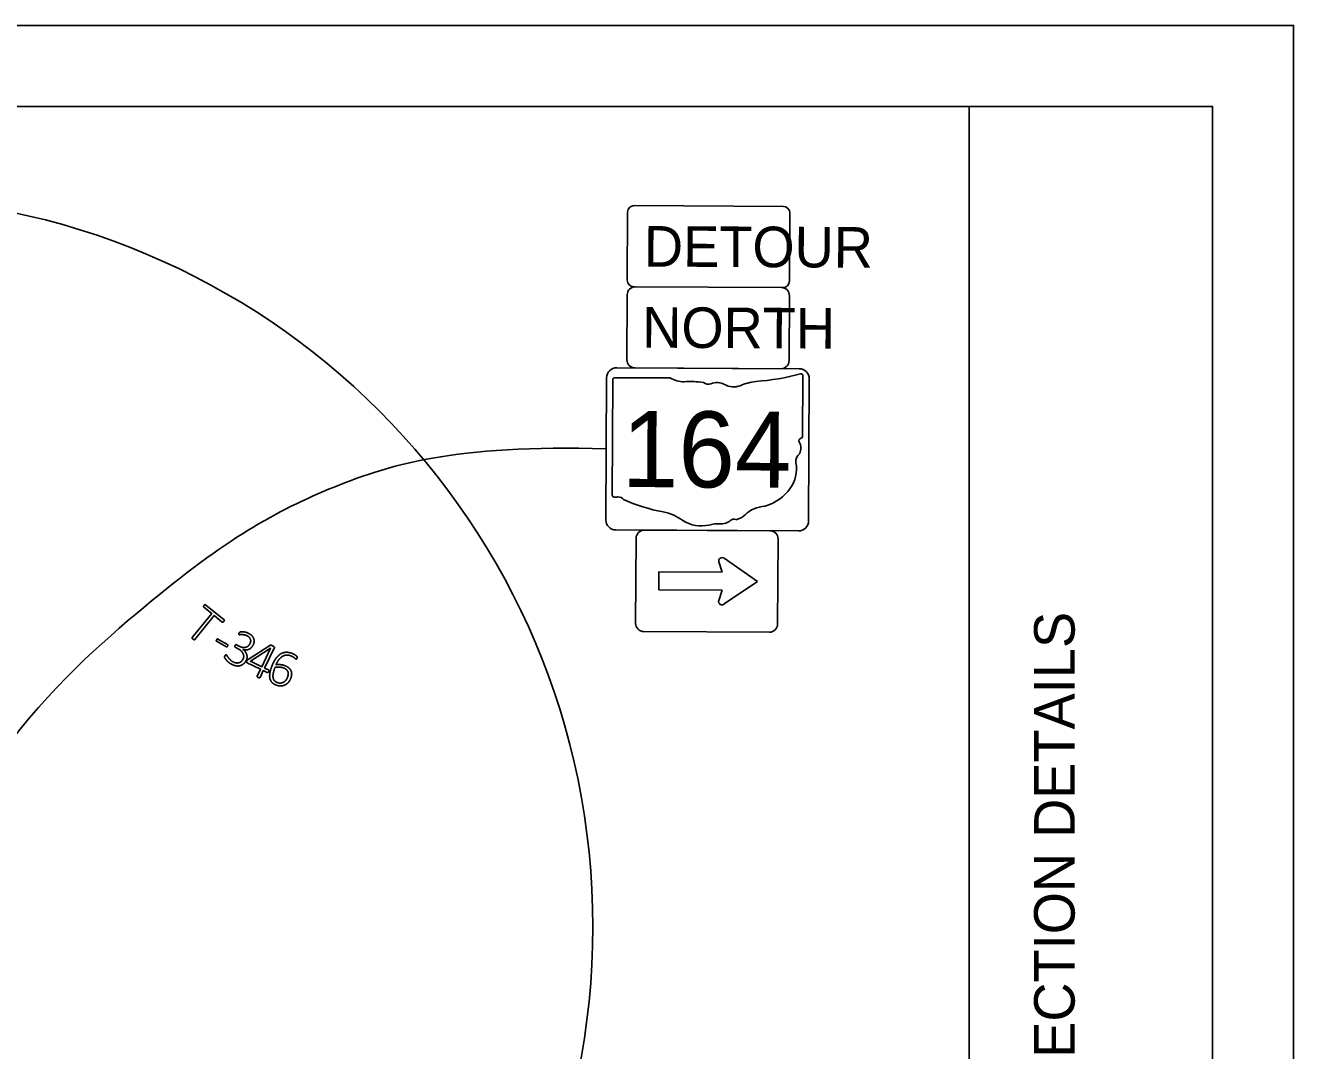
# Model space of a CAD drawing. Extents: x -202 to 1556, y 0 to 676.
# Drawn here: x 523.6 to 680, y 313.6 to 440 of the extents above; entities that cross this region are included whole.
import ezdxf

# ---------------------------------------------------------------- set-up
doc = ezdxf.new("R2010")
doc.units = 0
for name, color, linetype in [('Default', 7, 'Continuous'), ('GM_X_Minor_Lake', 7, 'Continuous'), ('GM_X_Minor_Lake_Text', 7, 'Continuous'), ('SH_Border', 7, 'Continuous'), ('SH_Cut_Line', 7, 'Continuous'), ('SH_Data', 7, 'Continuous')]:
    doc.layers.add(name, color=color, linetype=linetype)

msp = doc.modelspace()

# ---------------------------------------------------------------- linework, layer by layer
at = {"layer": 'Default'}
for p, q in [((545.84, 368.55), (548.12, 366.71)), ((548.09, 366.5), (548.09, 366.5)), ((548.4, 363.37), (547.2, 364.05)), ((547.36, 364.33), (548.56, 363.66)), ((548.56, 363.47), (548.56, 363.47)), ((549.86, 363.13), (549.5, 363.33)), ((549.67, 363.63), (549.99, 363.45)), ((550.45, 363.05), (550.45, 363.04)), ((553.76, 363.55), (551.1, 361.82)), ((550.83, 361.65), (550.83, 361.65)), ((553.63, 360.32), (553.63, 360.32)), ((555.93, 359.59), (555.93, 359.59)), ((556.34, 359.47), (556.34, 359.47))]:
    msp.add_line(p, q, dxfattribs=at)
for points in [[(544.2, 364.51), (546.6, 367.48), (545.62, 368.28)], [(547.9, 366.43), (546.91, 367.23), (544.51, 364.26)], [(553.59, 360.52), (553.11, 360.75), (554.32, 363.28)], [(550.96, 361.41), (552.61, 360.62), (552.19, 359.75)], [(552.55, 359.58), (552.96, 360.45), (553.45, 360.21)]]:
    msp.add_lwpolyline(points, dxfattribs=at)
msp.add_lwpolyline([(553.86, 363.21), (552.76, 360.92), (551.37, 361.59), (553.85, 363.21)], close=True, dxfattribs=at)
for points in [[(545.59, 368.36), (545.59, 368.38), (545.61, 368.41)], [(545.59, 368.31), (545.59, 368.34), (545.59, 368.36)], [(545.62, 368.28), (545.6, 368.29), (545.59, 368.31)], [(545.61, 368.41), (545.62, 368.44), (545.65, 368.48)], [(545.65, 368.48), (545.68, 368.51), (545.71, 368.53)], [(545.71, 368.53), (545.73, 368.56), (545.76, 368.57)], [(545.76, 368.57), (545.78, 368.58), (545.8, 368.57)], [(545.8, 368.57), (545.82, 368.57), (545.84, 368.55)], [(547.94, 366.41), (547.91, 366.41), (547.9, 366.43)], [(547.98, 366.42), (547.96, 366.41), (547.94, 366.41)], [(548.03, 366.45), (548.01, 366.42), (547.98, 366.42)], [(548.09, 366.5), (548.06, 366.47), (548.03, 366.45)], [(548.13, 366.57), (548.11, 366.54), (548.09, 366.5)], [(548.12, 366.71), (548.14, 366.69), (548.15, 366.67)], [(548.15, 366.62), (548.15, 366.6), (548.13, 366.57)], [(548.15, 366.67), (548.16, 366.65), (548.15, 366.62)], [(544.18, 364.48), (544.18, 364.5), (544.2, 364.51)], [(544.19, 364.44), (544.18, 364.46), (544.18, 364.48)], [(544.23, 364.39), (544.2, 364.42), (544.19, 364.44)], [(544.3, 364.32), (544.25, 364.36), (544.23, 364.39)], [(549.92, 364.94), (549.92, 364.96), (549.93, 364.99)], [(549.93, 364.9), (549.92, 364.91), (549.92, 364.94)], [(549.93, 364.99), (549.94, 365.02), (549.97, 365.07)], [(549.96, 364.88), (549.94, 364.89), (549.93, 364.9)], [(550.09, 364.87), (549.99, 364.86), (549.96, 364.88)], [(549.97, 365.07), (549.99, 365.1), (550.01, 365.13)], [(550.01, 365.13), (550.02, 365.15), (550.04, 365.16)], [(550.04, 365.16), (550.06, 365.18), (550.08, 365.19)], [(550.08, 365.19), (550.11, 365.2), (550.15, 365.21)], [(550.33, 364.88), (550.18, 364.88), (550.09, 364.87)], [(550.15, 365.21), (550.19, 365.22), (550.29, 365.23)], [(550.29, 365.23), (550.4, 365.24), (550.55, 365.22)], [(550.65, 364.85), (550.47, 364.88), (550.33, 364.88)], [(550.55, 365.22), (550.69, 365.2), (550.86, 365.15)], [(550.99, 364.72), (550.82, 364.82), (550.65, 364.85)], [(550.86, 365.15), (551.03, 365.1), (551.19, 365.01)], [(551.25, 364.51), (551.16, 364.63), (550.99, 364.72)], [(551.19, 365.01), (551.45, 364.86), (551.6, 364.69)], [(551.38, 364.26), (551.35, 364.39), (551.25, 364.51)], [(551.6, 364.69), (551.74, 364.52), (551.8, 364.33)], [(544.38, 364.27), (544.34, 364.29), (544.3, 364.32)], [(544.43, 364.24), (544.41, 364.25), (544.38, 364.27)], [(544.48, 364.24), (544.46, 364.23), (544.43, 364.24)], [(544.51, 364.26), (544.49, 364.25), (544.48, 364.24)], [(547.16, 364.11), (547.15, 364.16), (547.2, 364.24)], [(547.2, 364.05), (547.16, 364.07), (547.16, 364.11)], [(547.2, 364.24), (547.24, 364.32), (547.28, 364.34)], [(547.28, 364.34), (547.32, 364.36), (547.36, 364.33)], [(548.47, 363.37), (548.43, 363.35), (548.4, 363.37)], [(548.56, 363.47), (548.51, 363.39), (548.47, 363.37)], [(548.56, 363.66), (548.58, 363.65), (548.59, 363.63)], [(548.59, 363.54), (548.58, 363.51), (548.56, 363.47)], [(548.59, 363.63), (548.6, 363.62), (548.6, 363.59)], [(548.6, 363.59), (548.6, 363.57), (548.59, 363.54)], [(549.45, 363.41), (549.44, 363.44), (549.45, 363.47)], [(549.45, 363.47), (549.45, 363.51), (549.48, 363.55)], [(549.47, 363.36), (549.45, 363.38), (549.45, 363.41)], [(549.5, 363.33), (549.48, 363.34), (549.47, 363.36)], [(549.48, 363.55), (549.5, 363.59), (549.52, 363.61)], [(549.52, 363.61), (549.55, 363.63), (549.57, 363.64)], [(549.57, 363.64), (549.6, 363.65), (549.62, 363.65)], [(549.62, 363.65), (549.64, 363.65), (549.67, 363.63)], [(550.25, 362.84), (550.09, 363), (549.86, 363.13)], [(549.99, 363.45), (550.19, 363.34), (550.38, 363.3)], [(550.47, 362.51), (550.4, 362.68), (550.25, 362.84)], [(550.38, 363.3), (550.57, 363.26), (550.74, 363.3)], [(550.82, 362.98), (550.64, 362.98), (550.45, 363.05)], [(550.45, 363.04), (550.63, 362.92), (550.75, 362.75)], [(550.74, 363.3), (550.92, 363.34), (551.06, 363.44)], [(551.15, 363.05), (551, 362.99), (550.82, 362.98)], [(551.06, 363.44), (551.2, 363.55), (551.3, 363.73)], [(551.45, 363.25), (551.31, 363.12), (551.15, 363.05)], [(551.3, 363.73), (551.37, 363.85), (551.39, 363.99)], [(551.39, 363.99), (551.42, 364.13), (551.38, 364.26)], [(551.68, 363.55), (551.58, 363.37), (551.45, 363.25)], [(551.82, 363.94), (551.79, 363.74), (551.68, 363.55)], [(551.8, 364.33), (551.85, 364.14), (551.82, 363.94)], [(553.81, 363.57), (553.78, 363.57), (553.76, 363.55)], [(553.88, 363.57), (553.84, 363.58), (553.81, 363.57)], [(553.97, 363.55), (553.92, 363.57), (553.88, 363.57)], [(554.08, 363.5), (554.02, 363.53), (553.97, 363.55)], [(554.2, 363.44), (554.15, 363.47), (554.08, 363.5)], [(554.28, 363.38), (554.25, 363.41), (554.2, 363.44)], [(554.32, 363.32), (554.31, 363.35), (554.28, 363.38)], [(554.32, 363.28), (554.33, 363.3), (554.32, 363.32)], [(548.18, 362.09), (548.18, 362.12), (548.19, 362.14)], [(548.19, 362.04), (548.18, 362.07), (548.18, 362.09)], [(548.19, 362.14), (548.19, 362.17), (548.21, 362.2)], [(548.26, 361.92), (548.2, 362.01), (548.19, 362.04)], [(548.21, 362.2), (548.22, 362.24), (548.25, 362.28)], [(548.25, 362.28), (548.29, 362.37), (548.33, 362.39)], [(548.42, 361.72), (548.32, 361.83), (548.26, 361.92)], [(548.33, 362.39), (548.37, 362.41), (548.4, 362.39)], [(548.4, 362.39), (548.42, 362.38), (548.48, 362.29)], [(548.66, 361.48), (548.52, 361.6), (548.42, 361.72)], [(548.48, 362.29), (548.53, 362.19), (548.62, 362.07)], [(548.62, 362.07), (548.71, 361.94), (548.85, 361.8)], [(548.98, 361.26), (548.8, 361.36), (548.66, 361.48)], [(548.85, 361.8), (548.98, 361.66), (549.18, 361.54)], [(549.56, 361.03), (549.29, 361.09), (548.98, 361.26)], [(549.18, 361.54), (549.39, 361.43), (549.57, 361.39)], [(549.57, 361.39), (549.76, 361.36), (549.92, 361.4)], [(549.92, 361.4), (550.08, 361.44), (550.21, 361.54)], [(550.5, 361.26), (550.31, 361.1), (550.08, 361.04)], [(550.21, 361.54), (550.34, 361.65), (550.43, 361.81)], [(550.43, 361.81), (550.53, 361.98), (550.54, 362.16)], [(550.54, 362.16), (550.55, 362.33), (550.47, 362.51)], [(550.83, 361.65), (550.7, 361.41), (550.5, 361.26)], [(550.75, 362.75), (550.87, 362.58), (550.92, 362.4)], [(550.95, 362.02), (550.93, 361.83), (550.83, 361.65)], [(550.92, 361.62), (550.9, 361.57), (550.89, 361.54)], [(550.89, 361.54), (550.89, 361.51), (550.9, 361.48)], [(550.9, 361.48), (550.9, 361.46), (550.92, 361.44)], [(550.92, 362.4), (550.97, 362.22), (550.95, 362.02)], [(550.96, 361.69), (550.94, 361.66), (550.92, 361.62)], [(550.92, 361.44), (550.94, 361.42), (550.96, 361.41)], [(551, 361.74), (550.98, 361.71), (550.96, 361.69)], [(551.04, 361.78), (551.02, 361.76), (551, 361.74)], [(551.1, 361.82), (551.07, 361.8), (551.04, 361.78)], [(554.26, 361.55), (554.13, 361.29), (554.03, 361.03)], [(554.56, 362.01), (554.4, 361.8), (554.26, 361.55)], [(554.52, 361.16), (554.65, 361.47), (554.83, 361.73)], [(554.93, 362.38), (554.73, 362.22), (554.56, 362.01)], [(554.83, 361.73), (555.01, 361.98), (555.24, 362.15)], [(555.37, 362.63), (555.13, 362.55), (554.93, 362.38)], [(555.24, 362.15), (555.47, 362.31), (555.74, 362.35)], [(555.89, 362.7), (555.61, 362.71), (555.37, 362.63)], [(555.74, 362.35), (556.01, 362.39), (556.32, 362.27)], [(556.49, 362.57), (556.16, 362.69), (555.89, 362.7)], [(556.32, 362.27), (556.48, 362.21), (556.59, 362.14)], [(556.71, 362.47), (556.6, 362.53), (556.49, 362.57)], [(556.59, 362.14), (556.7, 362.08), (556.78, 362.02)], [(556.9, 362.35), (556.81, 362.41), (556.71, 362.47)], [(556.78, 362.02), (556.85, 361.96), (556.9, 361.91)], [(557.05, 362.24), (556.99, 362.29), (556.9, 362.35)], [(556.9, 361.91), (556.95, 361.87), (556.98, 361.86)], [(556.98, 361.86), (557, 361.85), (557.02, 361.85)], [(557.02, 361.85), (557.04, 361.86), (557.06, 361.87)], [(557.11, 362.16), (557.1, 362.19), (557.05, 362.24)], [(557.06, 361.87), (557.07, 361.89), (557.08, 361.92)], [(557.08, 361.92), (557.1, 361.94), (557.11, 361.98)], [(557.13, 362.12), (557.13, 362.14), (557.11, 362.16)], [(557.11, 361.98), (557.12, 362.01), (557.13, 362.03)], [(557.13, 362.08), (557.14, 362.1), (557.13, 362.12)], [(557.13, 362.03), (557.13, 362.06), (557.13, 362.08)], [(550.08, 361.04), (549.84, 360.98), (549.56, 361.03)], [(552.19, 359.75), (552.18, 359.74), (552.18, 359.72)], [(552.18, 359.72), (552.18, 359.7), (552.2, 359.68)], [(552.2, 359.68), (552.22, 359.66), (552.25, 359.64)], [(553.45, 360.21), (553.5, 360.19), (553.55, 360.22)], [(553.55, 360.22), (553.6, 360.25), (553.63, 360.32)], [(553.66, 360.44), (553.64, 360.5), (553.59, 360.52)], [(553.63, 360.32), (553.67, 360.39), (553.66, 360.44)], [(553.75, 359.98), (553.73, 359.74), (553.75, 359.54)], [(553.84, 360.47), (553.77, 360.21), (553.75, 359.98)], [(554.03, 361.03), (553.92, 360.74), (553.84, 360.47)], [(554.17, 359.55), (554.12, 359.78), (554.18, 360.09)], [(554.18, 360.09), (554.24, 360.4), (554.4, 360.83)], [(554.4, 360.83), (554.51, 360.86), (554.64, 360.87)], [(554.75, 361.19), (554.63, 361.18), (554.52, 361.16)], [(554.64, 360.87), (554.77, 360.88), (554.91, 360.88)], [(555.02, 361.18), (554.88, 361.19), (554.75, 361.19)], [(554.91, 360.88), (555.04, 360.87), (555.18, 360.84)], [(555.31, 361.14), (555.16, 361.17), (555.02, 361.18)], [(555.18, 360.84), (555.32, 360.82), (555.45, 360.77)], [(555.61, 361.05), (555.46, 361.11), (555.31, 361.14)], [(555.45, 360.77), (555.68, 360.68), (555.81, 360.55)], [(556.13, 360.75), (555.95, 360.93), (555.61, 361.05)], [(555.81, 360.55), (555.95, 360.43), (556, 360.28)], [(556.03, 359.96), (556, 359.78), (555.93, 359.59)], [(556, 360.28), (556.05, 360.13), (556.03, 359.96)], [(556.4, 360.37), (556.32, 360.58), (556.13, 360.75)], [(556.34, 359.47), (556.43, 359.71), (556.45, 359.93)], [(556.45, 359.93), (556.47, 360.16), (556.4, 360.37)], [(552.25, 359.64), (552.28, 359.62), (552.33, 359.59)], [(552.33, 359.59), (552.38, 359.57), (552.42, 359.56)], [(552.42, 359.56), (552.45, 359.55), (552.48, 359.55)], [(552.48, 359.55), (552.5, 359.55), (552.52, 359.56)], [(552.52, 359.56), (552.54, 359.57), (552.55, 359.58)], [(553.75, 359.54), (553.78, 359.35), (553.88, 359.18)], [(553.88, 359.18), (553.97, 359.02), (554.13, 358.89)], [(554.13, 358.89), (554.28, 358.76), (554.51, 358.67)], [(554.34, 359.19), (554.21, 359.33), (554.17, 359.55)], [(554.69, 358.97), (554.47, 359.05), (554.34, 359.19)], [(554.51, 358.67), (554.87, 358.53), (555.16, 358.55)], [(555.11, 358.9), (554.92, 358.88), (554.69, 358.97)], [(555.47, 359.02), (555.31, 358.93), (555.11, 358.9)], [(555.16, 358.55), (555.45, 358.57), (555.68, 358.7)], [(555.75, 359.27), (555.63, 359.12), (555.47, 359.02)], [(555.68, 358.7), (555.92, 358.82), (556.08, 359.03)], [(555.93, 359.59), (555.87, 359.42), (555.75, 359.27)], [(556.08, 359.03), (556.24, 359.24), (556.34, 359.47)]]:
    msp.add_open_spline(points, degree=2, dxfattribs=at)
at = {"layer": 'GM_X_Minor_Lake'}
for p, q in [((597.79, 398.77), (597.83, 406.77)), ((598.84, 407.77), (616.84, 407.67)), ((617.83, 406.67), (617.79, 398.67)), ((616.79, 397.67), (598.79, 397.77)), ((596.06, 396.31), (595.98, 382.08)), ((603.15, 396.52), (596.29, 396.55)), ((619.46, 389.34), (619.5, 396.79)), ((619.46, 389.34), (619.46, 389.34))]:
    msp.add_line(p, q, dxfattribs=at)
for points in [[(617.09, 417.67), (598.69, 417.77)], [(597.88, 416.97), (597.84, 408.57)], [(617.84, 408.47), (617.88, 416.87)], [(598.64, 407.77), (617.04, 407.67)], [(596.54, 397.78), (619.04, 397.66)], [(595.19, 379.04), (595.28, 396.54)], [(620.28, 396.41), (620.19, 378.91)], [(618.93, 377.66), (596.43, 377.78)]]:
    msp.add_lwpolyline(points, dxfattribs=at)
for centre, radius, start, end in [((598.68, 416.97), 0.8, 89.7036, 179.7036), ((617.08, 416.87), 0.8, 359.7036, 89.7036), ((598.64, 408.57), 0.8, 179.7036, 269.7036), ((617.04, 408.47), 0.8, 269.7036, 359.7036), ((598.83, 406.77), 1, 89.7036, 179.7036), ((616.83, 406.67), 1, 359.7036, 89.7036), ((596.53, 396.53), 1.25, 89.7036, 179.7036), ((598.79, 398.77), 1, 179.7036, 269.7036), ((616.79, 398.67), 1, 269.7036, 359.7036), ((619.03, 396.41), 1.25, 359.7036, 89.7036), ((596.44, 379.03), 1.25, 179.7036, 269.7036), ((618.94, 378.91), 1.25, 269.7036, 359.7036)]:
    msp.add_arc(centre, radius, start, end, dxfattribs=at)
for centre, major_axis, start_param, end_param in [((596.33, 396.34), (0.272, -0.001), 1.712693, 3.28349), ((604.8, 398.16), (2.63, -0.01), 4.042523, 4.731795), ((605.62, 388.52), (9.45, -0.05), 1.404758, 1.657858), ((607.81, 396.35), (0.76, -0.004), 3.836095, 5.185415), ((608.91, 394.7), (1.58, -0.01), 0.950623, 2.079405), ((610.96, 396.95), (1.9, -0.01), 4.081561, 5.145723), ((614.3, 392.11), (5, -0.03), 1.699011, 2.107814), ((611.25, 415.88), (24.85, -0.13), 4.814394, 5.042369), ((619.24, 396.82), (0.261, -0.001), 6.141152, 7.989035), ((619.4, 388.8), (0.404, -0.002), 1.883978, 3.671073), ((616.82, 387.87), (2.42, -0.01), 5.934695, 6.695948), ((619.18, 389.32), (0.279, -0.001), 5.05454, 6.418171), ((620.38, 386.22), (1.76, -0.01), 2.387724, 3.262537), ((612.48, 385.32), (6.22, -0.03), 5.101752, 6.440018), ((596.26, 382.05), (0.274, -0.001), 3.00124, 4.508301), ((596.3, 383.5), (2.09, -0.01), 4.665946, 4.897461), ((596.72, 381.25), (0.754, -0.004), 0.519207, 1.627899), ((606.3, 393.99), (17.95, -0.09), 4.195997, 4.488961), ((600.86, 375.66), (5.62, -0.03), 0.823519, 1.323587), ((615.07, 377.99), (3.4, -0.02), 1.647645, 2.488434), ((606.96, 381.13), (3.56, -0.02), 4.026481, 4.996735), ((608.99, 376.2), (2.93, -0.02), 1.495662, 1.94098), ((609.27, 380.05), (1.9, -0.01), 4.691044, 5.507374), ((610.98, 378.67), (0.535, -0.003), 1.147584, 2.315152), ((610.77, 380.62), (2.01, -0.01), 4.937069, 5.64225)]:
    msp.add_ellipse(centre, major_axis=major_axis, ratio=0.8, start_param=start_param, end_param=end_param, dxfattribs=at)
at = {"layer": 'GM_X_Minor_Lake_Text'}
for p, q in [((599.93, 377.76), (615.43, 377.68)), ((598.87, 366.27), (598.93, 376.77)), ((616.43, 376.68), (616.37, 366.18)), ((609.14, 373.84), (609.53, 372.56)), ((613.9, 371.44), (609.78, 374.31)), ((601.72, 372.6), (601.71, 370.41)), ((609.53, 372.56), (601.72, 372.6)), ((609.8, 368.67), (613.9, 371.44)), ((601.71, 370.41), (609.52, 370.37)), ((609.52, 370.37), (609.11, 369.09)), ((615.37, 365.18), (599.87, 365.26))]:
    msp.add_line(p, q, dxfattribs=at)
for centre, radius, start, end in [((599.93, 376.76), 1, 89.7036, 179.7036), ((615.43, 376.68), 1, 359.7036, 89.7036), ((609.54, 373.96), 0.417, 55.1148, 196.9082), ((609.51, 368.96), 0.417, 162.499, 314.7132), ((599.87, 366.26), 1, 179.7036, 269.7036), ((615.37, 366.18), 1, 269.7036, 359.7036)]:
    msp.add_arc(centre, radius, start, end, dxfattribs=at)
at = {"layer": 'SH_Border'}
msp.add_line((640, 10), (640, 430), dxfattribs=at)
msp.add_lwpolyline([(30, 430), (670, 430), (670, 10), (30, 10)], close=True, dxfattribs=at)
at = {"layer": 'SH_Cut_Line'}
msp.add_lwpolyline([(0, 0), (680, 0), (680, 440), (0, 440)], close=True, dxfattribs=at)
at = {"layer": 'SH_Data'}
msp.add_circle((503.59, 328.84), 90, dxfattribs=at)
msp.add_open_spline([(595.23, 387.79), (576.58, 388.37), (559.82, 383.23), (541.84, 372.9), (511.42, 344.06), (505.76, 315.08)], degree=3, dxfattribs=at)

# ---------------------------------------------------------------- texts
at = {"layer": 'GM_X_Minor_Lake'}
for s, height, p in [('DETOUR', 5, (599.88, 410.26)), ('NORTH', 5, (599.67, 400.26)), ('164', 9.375, (597.14, 383.08))]:
    msp.add_text(s, height=height, rotation=359.7036, dxfattribs=at).set_placement(p)
at = {"layer": 'SH_Data'}
msp.add_text('MAINTENANCE OF TRAFFIC - DETOUR INTERSECTION DETAILS', height=5, rotation=90, dxfattribs=at).set_placement((653, 162.26))

doc.saveas('drawing.dxf')
